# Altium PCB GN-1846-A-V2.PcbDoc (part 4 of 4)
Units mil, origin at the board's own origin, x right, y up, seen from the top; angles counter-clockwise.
Board outline 11624.17 x 2384.02 mil, 4 copper layers (Top, GND, VCC, Bottom), stack 40.7 mil thick; 450 components, 346 nets, 1652 pads, 832 vias.
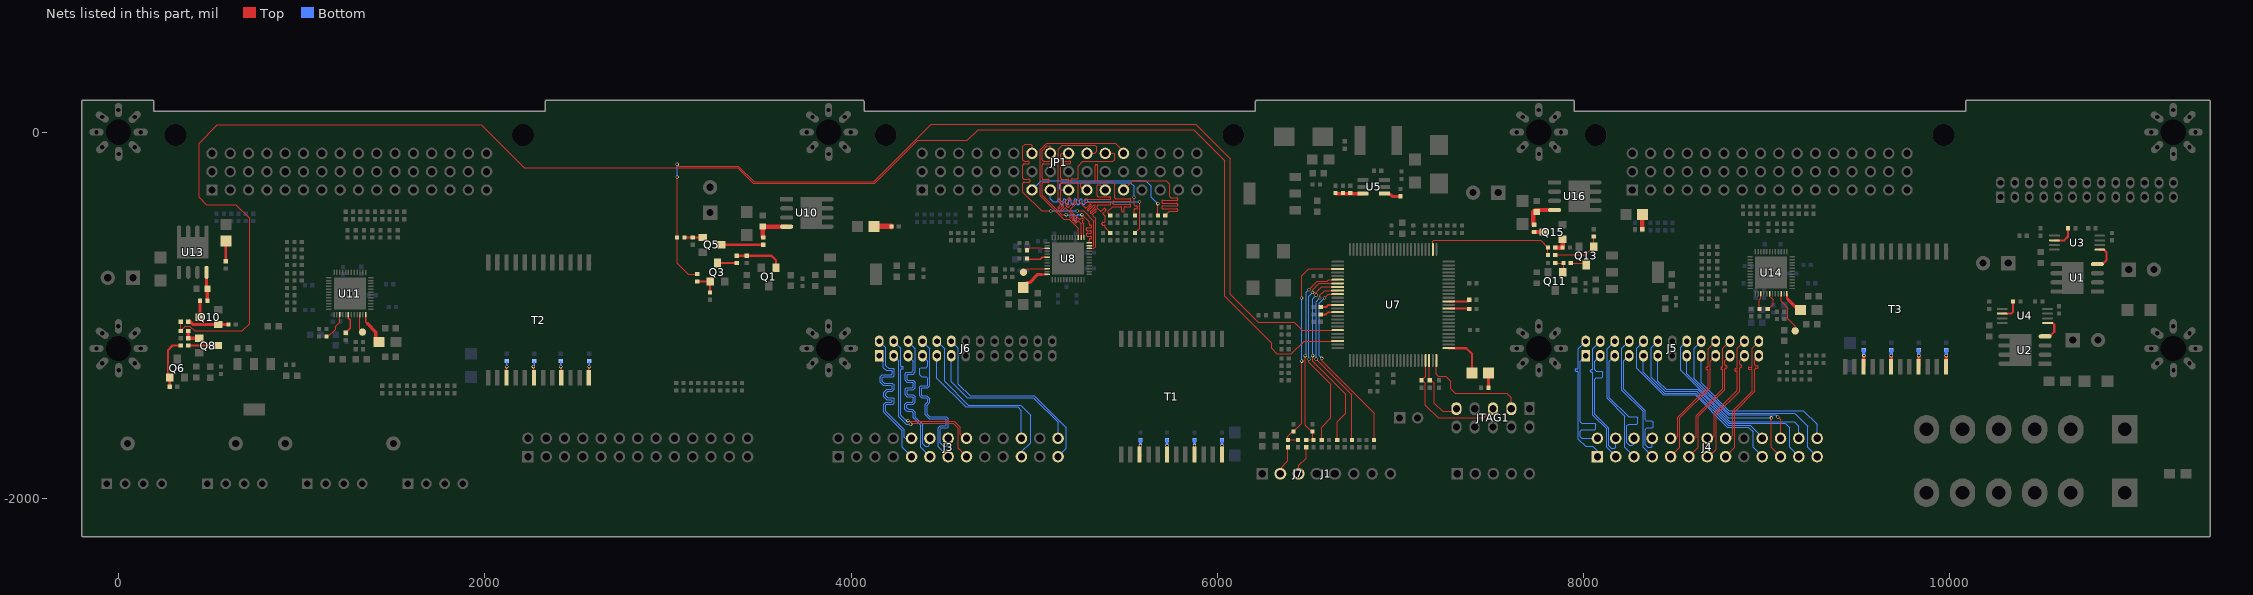
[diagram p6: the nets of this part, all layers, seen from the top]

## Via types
v1: diameter 18, hole 12, Top to Bottom, 768 vias
v2: diameter 24, hole 16, Top to Bottom, 34 vias
v3: diameter 30, hole 20, Top to Bottom, 27 vias
v4: diameter 40, hole 30, Top to Bottom, 2 vias
v5: diameter 24, hole 14, Top to Bottom, 1 vias

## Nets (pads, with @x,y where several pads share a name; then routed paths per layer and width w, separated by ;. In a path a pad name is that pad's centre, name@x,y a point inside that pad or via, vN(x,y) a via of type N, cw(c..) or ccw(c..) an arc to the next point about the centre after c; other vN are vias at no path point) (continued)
NetJTAG1_3: JTAG1.3 U7.25 | length 620.9
  Top w5: U7.25@7196.03,-1246.56 7196.03,-1321.03 7207,-1332 7247,-1332 7275,-1360 7275,-1401 7299,-1425 7580,-1425 7605,-1450 JTAG1.3@7605,-1510
NetJTAG1_5: JTAG1.5 R20.2 U7.22 | length 678.5
  Top w5: R20.2@7115,-1355 7136.97,-1333.03 U7.22@7136.97,-1246.56 ; R20.2@7120,-1355 7135,-1370 7135,-1490 7205,-1560 7455,-1560 JTAG1.5@7505,-1510
NetJTAG1_9: JTAG1.9 R21.1 U7.23 | length 378.8
  Top w5: U7.23@7156.66,-1246.56 7156.66,-1343.34 7185,-1371.68 7185,-1480 7230,-1525 JTAG1.9@7300,-1525
NetL3_2: L3.2 U8.48 | length 180.8
  Top w10: 5040,-776.61 U8.48@5070.04,-776.61
  Top w18: L3.2@4922.98,-858 4960,-820.98 4975.03,-820.98 5019.4,-776.61 5040,-776.61
NetL4_2: L4.2 U11.48 | length 179.5
  Top w10: U11.48@1349.76,-995.8 1349.76,-1036.53 1359.93,-1046.69
  Top w18: 1359.93,-1046.69 1405,-1091.77 1405,-1127 L4.2@1423,-1145
NetL5_2: L5.2 U14.48 | length 124
  Top w5: 9115,-911.85 9116.98,-913.83
  Top w10: U14.48@9110,-881.81 9110,-906.85 9115,-911.85
  Top w18: 9116.98,-913.83 L5.2@9180,-976.85
NetLED1_K: LED1.K R81.2 | length 94.8
  Top w30: LED1.K@4125.32,-514.61 4219.61,-514.61 R81.2@4220,-515
NetLED2_K: LED2.K R141.2 | length 109.8
  Top w15: R141.2@585,-705 585,-595.71 LED2.K@585.39,-595.32
NetLED3_A: LED3.A U7.26 | length 244.4
  Top w12: U7.26@7262.96,-1179.64 7359.64,-1179.64 7390.32,-1210.32 LED3.A@7390.32,-1314.61
NetLED3_K: LED3.K R7.2 | length 80.5
  Top w15: R7.2@7480,-1395 7480,-1314.94 LED3.K@7480.32,-1314.61
NetLED4_K: LED4.K R201.2 | length 80.5
  Top w24: R201.2@8320,-530 8320.32,-529.68 LED4.K@8320.32,-449.61
NetQ1_1: Q1.1 R58.2 R65.1 | length 265.4
  Top w12: R65.1@3375,-675 3565,-675 3590,-700 Q1.1@3590,-740
NetQ3_1: Q3.1 R73.1 R74.2 | length 130
  Top w12: R73.1@3160,-815 Q3.1@3230,-815 R74.2@3230,-875
NetQ3_3: Q3.3 R65.2 | length 105
  Top w12: Q3.3@3270,-715 R65.2@3375,-715
NetQ5_1: Q5.1 R82.1 R83.2 | length 100
  Top w12: R82.1@3090,-575 Q5.1@3190,-575
NetQ5_3: Q5.3 R80.1 | length 250
  Top w12: Q5.3@3270,-615 R80.1@3520,-615
NetQ6_1: Q6.1 R118.2 R127.1 | length 270.4
  Top w12: Q6.1@270,-1330 270,-1190 295,-1165 R127.1@340,-1165 ; R118.2@280,-1390 Q6.1@280,-1340
NetQ8_1: Q8.1 R133.1 R134.2 | length 100
  Top w18: R133.1@380,-1085 R134.2@380,-1125 Q8.1@440,-1125
NetQ8_3: Q8.3 R127.2 | length 160
  Top w12: R127.2@380,-1165 Q8.3@540,-1165
NetQ10_1: Q10.1 R142.1 R143.2 | length 219.7
  Top w18: R142.1@387.5,-1032.5 405,-1050 Q10.1@545,-1050 R143.2@600,-1050
NetQ10_3: Q10.3 R140.1 | length 90
  Top w18: Q10.3@445,-1010 R140.1@445,-920
NetQ11_1: Q11.1 R178.2 R186.1 | length 97.1
  Top w5: R178.2@7845,-715 R186.1@7890,-715 7890,-760 Q11.1@7885,-765
NetQ13_1: Q13.1 R193.1 R194.2 | length 283.6
  Top w5: R193.1@7845,-670 8010,-670 Q13.1@8055,-625 R194.2@8055,-570
NetQ13_3: Q13.3 R186.2 | length 89.1
  Top w5: R186.2@7930,-715 8005,-715 Q13.3@8015,-725
NetQ15_1: Q15.1 R202.1 R203.2 | length 85
  Top w24: R202.1@7845,-630 R203.2@7885,-630 Q15.1@7885,-585
NetQ15_3: Q15.3 R200.1 | length 60
  Top w24: R200.1@7725,-545 Q15.3@7785,-545
NetR5_1: R5.1 U3.2 | length 128.3
  Top w12: U3.2@10570.23,-590.64 10624.36,-590.64 10645,-570 R5.1@10645,-525
NetR6_1: R6.1 U4.2 | length 119.2
  Top w12: U4.2@10285.23,-990.64 10334.36,-990.64 10345,-980 R6.1@10345,-925
NetR8_2: R8.2 U5.4 | length 93.3
  Top w16: U5.4@6912.72,-335.58 6940.58,-335.58 6955,-350 R8.2@7000,-350
NetR9_2: R9.2 R10.2 R11.1 U5.3 | length 150.4
  Top w18: R10.2@6645.51,-332.35 6648.75,-335.58 U5.3@6794.6,-335.58
NetR12_1: R12.1 R425.2 R432.2 U7.78 | length 1196.6
  Top w5: R425.2@6440,-1680 R12.1@6385,-1680 6385,-1660 6410,-1635 R432.2@6415,-1635 6460,-1590 v1(6460,-1250) ; v1(6460,-905) 6460,-785 6498.43,-746.57 U7.78@6656.66,-746.57
  Bottom w5: v1(6460,-1250) v1(6460,-905)
NetR13_1: R13.1 R424.2 R433.2 U7.81 | length 1069
  Top w5: v1(6480,-1220) 6480,-1600 6515,-1635 R433.2@6520,-1635 6520,-1675 R424.2@6525,-1680 R13.1@6485,-1680 ; v1(6500,-860) 6545,-815 6600,-815 6609.38,-805.62 U7.81@6656.66,-805.62
  Bottom w5: v1(6480,-1220) 6485,-1215 6485,-875 v1(6500,-860)
NetR14_1: R14.1 U7.82 | length 1049.6
  Top w5: v1(6500,-1240) 6500,-1255 6620,-1375 6620,-1560 6570,-1610 R14.1@6570,-1680 ; v1(6520,-875) 6520,-860.31 6555,-825.31 U7.82@6656.66,-825.31
  Bottom w5: v1(6500,-1240) 6500,-895 v1(6520,-875)
NetR15_1: R15.1 U7.83 | length 1035.6
  Top w5: v1(6520,-1220) 6520,-1250 6700,-1430 6700,-1535 6655,-1580 R15.1@6655,-1680 ; v1(6540,-890) 6540,-874.99 6570,-844.99 U7.83@6656.66,-844.99
  Bottom w5: v1(6520,-1220) 6520,-910 v1(6540,-890)
NetR16_1: R16.1 U7.84 | length 986.2
  Top w5: v1(6540,-1240) 6735,-1435 R16.1@6735,-1680 ; v1(6560,-905) 6560,-890 6585.32,-864.68 U7.84@6656.66,-864.68
  Bottom w5: v1(6540,-1240) 6540,-925 v1(6560,-905)
NetR17_2: R17.2 U7.88 | length 96.5
  Top w10: R17.2@6565,-955 6593.42,-955 6605,-943.42 U7.88@6656.66,-943.42
NetR18_2: R18.2 U7.90 | length 96.7
  Top w10: R18.2@6565,-995 6592.79,-995 6605,-982.79 U7.90@6656.66,-982.79
NetR22_1: R22.1 U7.37 | length 117.5
  Top w10: U7.37@7262.96,-963.1 R22.1@7380.41,-963.1
NetR23_1: R23.1 U7.39 | length 112.3
  Top w10: U7.39@7262.96,-923.73 R23.1@7375.26,-923.73
NetR24_1: R24.1 T1.15 | length 89.8
  Top w15: v1@5576.14,-1713.86 5576.14,-1770.8 T1.15@5578.15,-1768.79
  Bottom w15: v1(5580,-1710) R24.1@5580,-1680
NetR25_1: R25.1 T1.18 | length 93.9
  Top w15: T1.18@5723.15,-1767.81 5726.14,-1770.8 v1@5726.14,-1711.14
  Bottom w15: v1(5725,-1710) R25.1@5725,-1680
NetR26_1: R26.1 T1.21 | length 92.5
  Top w15: v1@5876.14,-1711.14 5876.14,-1770.8 T1.21@5878.15,-1768.79
  Bottom w15: v1(5875,-1710) R26.1@5875,-1680
NetR32_1: R32.1 T1.24 | length 92.5
  Top w15: v1@6026.14,-1711.14 6026.14,-1770.8 T1.24@6028.15,-1768.79
  Bottom w15: v1(6025,-1710) R32.1@6025,-1680
NetR39_2: R39.2 U8.42 | length 147.6
  Top w8: R39.2@4960,-690 4964.16,-694.16 5005,-694.16 ; 4974.16,-694.16 5005,-694.16 ; U8.42@5070.04,-682.13 5043.88,-682.13 5031.85,-694.16 5005,-694.16
NetR43_2: R43.2 U8.39 | length 117.9
  Top w5: R43.2@4960,-645 4974.5,-630.5 5038.19,-630.5 5042.57,-634.88 U8.39@5070.04,-634.88
NetR73_2: R73.2 R82.2 U7.95 | length 5349.8
  Top w5: v1(3050,-245) R82.2@3050,-575 3050,-715 3110,-775 R73.2@3160,-775 ; v1(3050,-175) 3060,-185 3385,-185 3470,-270 4125,-270 4438.16,43.16 5882.55,43.16 6070,-144.29 6070,-884.29 6223.71,-1038 6420,-1038 6463.21,-1081.21 U7.95@6656.66,-1081.21
  Bottom w5: v1(3050,-245) v1(3050,-175)
NetR77_1: R77.1 R80.2 U10.4 | length 189.9
  Top w24: R80.2@3520,-575 3518.15,-573.15 R77.1@3518.15,-515.84 U10.4@3648.15,-515.84
NetR84_1: R84.1 T2.15 | length 91.6
  Top w8: T2.15@2118.15,-1340.8 2118.15,-1281.85 v1(2120,-1280)
  Bottom w8: v1(2120,-1280) R84.1@2120,-1250
NetR85_1: R85.1 T2.18 | length 89.7
  Top w8: T2.18@2268.15,-1340.8 v1@2268.15,-1283.15
  Bottom w8: v1(2265,-1280) 2270,-1275 R85.1@2270,-1250
NetR86_1: R86.1 T2.21 | length 92.1
  Top w8: v1(2415,-1280) 2418.15,-1283.15 T2.21@2418.15,-1340.8
  Bottom w8: v1(2415,-1280) R86.1@2415,-1250
NetR92_1: R92.1 T2.24 | length 91.6
  Top w8: T2.24@2568.15,-1340.8 2568.15,-1281.85 v1(2570,-1280)
  Bottom w8: v1(2570,-1280) R92.1@2570,-1250
NetR96_2: R96.2 U11.42 | length 113.6
  Top w8: R96.2@1240,-1095 1265,-1070 1265,-1024.72 1255.28,-1015 U11.42@1255.28,-995.8
NetR100_2: R100.2 U11.39 | length 155.3
  Top w5: R100.2@1135,-1115 1145,-1115 1185,-1075 1185,-1060 1208.03,-1036.97 U11.39@1208.03,-995.8
NetR133_2: R133.2 R142.2 U7.98 | length 9147.6
  Top w5: R142.2@340,-1040 R133.2@340,-1085 365,-1060 390,-1060 415,-1085 675,-1085 715,-1045 715,-470 640,-395 480,-395 440,-355 440,-60 540,40 1980,40 2215,-195 3380.86,-195 3465.86,-280 4129.14,-280 4364.14,-45 4635,-45 4693.16,13.16 5870.13,13.16 6040,-156.72 6040,-896.72 6296,-1152.72 6296,-1181 6325,-1210 6404,-1210 6473.73,-1140.27 U7.98@6656.66,-1140.27
NetR136_1: R136.1 R140.2 U13.4 | length 159.6
  Top w18: U13.4@480.24,-765.21 480.24,-855 R136.1@485,-855 R140.2@485,-920
NetR144_1: R144.1 T3.15 | length 91.6
  Top w18: T3.15@9528.15,-1280.8 9530,-1278.95 v1(9530,-1220)
  Bottom w18: v1(9530,-1220) R144.1@9530,-1190
NetR145_1: R145.1 T3.18 | length 91.6
  Top w18: T3.18@9678.15,-1280.8 9680,-1278.95 v1(9680,-1220)
  Bottom w18: v1(9680,-1220) R145.1@9680,-1190
NetR146_1: R146.1 T3.21 | length 91.6
  Top w18: T3.21@9828.15,-1280.8 9830,-1278.95 v1(9830,-1220)
  Bottom w18: v1(9830,-1220) R146.1@9830,-1190
NetR152_1: R152.1 T3.24 | length 91.6
  Top w18: T3.24@9978.15,-1280.8 9980,-1278.95 v1(9980,-1220)
  Bottom w18: v1(9980,-1220) R152.1@9980,-1190
NetR156_2: R156.2 U14.42 | length 106.6
  Top w5: R156.2@9005,-965 9010,-965 9035,-940 9035,-915 9015.52,-895.52 U14.42@9015.52,-881.81
NetR160_2: R160.2 U14.39 | length 86.8
  Top w5: R160.2@8960,-965 8960,-915 8968.27,-906.73 U14.39@8968.27,-881.81 U14.39@8968.39,-881.93
NetR193_2: R193.2 R202.2 U7.52 | length 731.3
  Top w5: U7.52@7176.34,-640.27 7176.34,-595.66 7181,-591 7766,-591 R202.2@7805,-630 R193.2@7805,-670
NetR197_1: R197.1 R200.2 U16.4 | length 190.4
  Top w24: R200.2@7725,-505 7725,-435 7735.16,-424.84 U16.4@7841.15,-424.84
NetR303_1: R303.1 U7.85 | length 993.1
  Top w5: v1(6570,-1235) 6570,-1249.14 6856.5,-1535.64 6856.5,-1678.5 R303.1@6855,-1680 ; v1(6585,-905) 6605.64,-884.36 U7.85@6656.66,-884.36
  Bottom w5: v1(6570,-1235) 6555,-1220 6555,-935 v1(6585,-905)
NetTP1_1: TP1.1 U8.46 | length 136.6
  Top w5: TP1.1@4941.59,-764.87 4961.34,-745.12 U8.46@5070.04,-745.12
NetTP2_1: TP2.1 U11.46 | length 101.4
  Top w5: U11.46@1318.27,-995.8 1318.27,-1077.89 TP2.1@1331.95,-1091.57
NetTP3_1: TP3.1 U14.46 | length 234.9
  Top w5: U14.46@9078.51,-881.81 9078.51,-923.51 9115,-960 9115,-1020 9155,-1060 TP3.1@9155,-1085
NetU1_4: U1.4 U3.5 | length 145.5
  Top w12: U1.4@10805,-720 10835,-720 10855,-700 10855,-655 10841.82,-641.82 U3.5@10818.26,-641.82
NetU2_4: U2.4 U4.5 | length 194
  Top w10: U2.4@10500,-1115 U2.4@10520,-1115 U2.4@10545,-1115 ; U4.5@10523.26,-1041.82 U4.5@10533.26,-1041.82 U4.5@10556.82,-1041.82
  Top w12: U4.5@10533.26,-1041.82 10561.82,-1041.82 10570,-1050 10570,-1090 U2.4@10545,-1115
RGMII_RXCK: JP1.C11 R27.1 | length 840.3
  Top w5: 5367.57,-430.16 cw(c5363.86,-426.44) 5360.16,-430.16 5345,-415 5345,-402.75 cw(c5350.25,-402.75) 5350.25,-397.5 5412.75,-397.5 ccw(c5412.75,-392.25) 5418,-392.25 5418,-387.75 ccw(c5412.75,-387.75) 5412.75,-382.5 5277.25,-382.5 cw(c5277.25,-377.25) 5272,-377.25 5272,-372.75 cw(c5277.25,-372.75) 5277.25,-367.5 5412.75,-367.5 ccw(c5412.75,-362.25) 5418,-362.25 5418,-357.75 ccw(c5412.75,-357.75) 5412.75,-352.5 5350.25,-352.5 cw(c5350.25,-347.25) 5345,-347.25 5345,-290 5347.39,-287.61 5360,-287.61 JP1.C11@5387.8,-315.41 ; 5367.57,-430.15 5379.95,-417.78 ; 5379.96,-417.77 cw(c5383.66,-421.49) 5387.36,-417.77 ; 5387.37,-417.78 5390.56,-420.96 cw(c5386.84,-424.67) 5390.56,-428.37 5375,-443.94 ccw(c5375.53,-444.47) 5375,-445 5387.8,-457.8 5387.8,-487.25 cw(c5382.55,-487.25) 5382.55,-492.5 5375.05,-492.5 ccw(c5375.05,-497.75) 5369.8,-497.75 5369.8,-502.25 ccw(c5375.05,-502.25) 5375.05,-507.5 5382.55,-507.5 cw(c5382.55,-512.75) 5387.8,-512.75 5387.8,-522.8 R27.1@5415,-550
RGMII_RXD0: JP1.C7 R29.1 | length 860
  Top w5: R29.1@5675,-455 v1(5675,-390)
  Bottom w5: JP1.C7@4987.8,-315.41 5038.2,-265 5610,-265 5640,-295 5640,-355 v1(5675,-390)
RGMII_RXD1: JP1.C8 R30.1 | length 977
  Top w5: R30.1@5550,-550 5575,-525 v1(5575,-380)
  Bottom w5: JP1.C8@5087.8,-315.41 5087.8,-362.8 5105,-380 5120,-380 ccw(c5120,-372.5) 5127.5,-372.5 cw(c5135,-372.5) 5135,-365 cw(c5135,-372.5) 5142.5,-372.5 5142.5,-387.5 ccw(c5150,-387.5) 5150,-395 ccw(c5150,-387.5) 5157.5,-387.5 5157.5,-372.5 cw(c5165,-372.5) 5165,-365 cw(c5165,-372.5) 5172.5,-372.5 5172.5,-387.5 ccw(c5180,-387.5) 5180,-395 ccw(c5180,-387.5) 5187.5,-387.5 5187.5,-372.5 cw(c5195,-372.5) 5195,-365 cw(c5195,-372.5) 5202.5,-372.5 5202.5,-387.5 ccw(c5210,-387.5) 5210,-395 ccw(c5210,-387.5) 5217.5,-387.5 5217.5,-372.5 cw(c5225,-372.5) 5225,-365 cw(c5225,-372.5) 5232.5,-372.5 5232.5,-387.5 ccw(c5240,-387.5) 5240,-395 ccw(c5240,-387.5) 5247.5,-387.5 5247.5,-372.5 cw(c5255,-372.5) 5255,-365 cw(c5255,-372.5) 5262.5,-372.5 5262.5,-387.5 ccw(c5270,-387.5) 5270,-395 ccw(c5270,-387.5) 5277.5,-387.5 5277.5,-372.5 cw(c5285,-372.5) 5285,-365 cw(c5285,-372.5) 5292.5,-372.5 5292.5,-377.5 ccw(c5295,-377.5) 5295,-380 v1(5575,-380)
RGMII_RXD2: JP1.C9 R31.1 | length 678.2
  Top w5: R31.1@5545,-450 5545,-422.75 cw(c5550.25,-422.75) 5550.25,-417.5 5558.75,-417.5 ccw(c5558.75,-412.25) 5564,-412.25 5564,-407.75 ccw(c5558.75,-407.75) 5558.75,-402.5 5550.25,-402.5 cw(c5550.25,-397.25) 5545,-397.25 v1(5545,-355)
  Bottom w5: JP1.C9@5189.59,-315.41 JP1.C9@5187.8,-315.41 5145.41,-315.41 5140,-310 5140,-285 5150,-275 5525,-275 5545,-295 v1(5545,-355)
RGMII_RXD3: JP1.C10 R33.1 | length 1031.8
  Top w5: JP1.C10@5287.8,-315.41 5270.41,-315.41 5255,-300 5255,-280 5265,-270 5327.25,-270 ccw(c5327.25,-264.75) 5332.5,-264.75 5332.5,-182.25 cw(c5337.75,-182.25) 5337.75,-177 5342.25,-177 cw(c5342.25,-182.25) 5347.5,-182.25 5347.5,-264.75 ccw(c5352.75,-264.75) 5352.75,-270 5425,-270 5440,-285 5440,-357.25 ccw(c5445.25,-357.25) 5445.25,-362.5 5522.75,-362.5 cw(c5522.75,-367.75) 5528,-367.75 5528,-372.25 cw(c5522.75,-372.25) 5522.75,-377.5 5434.24,-377.5 ccw(c5434.24,-382.75) 5428.99,-382.75 5428.99,-387.25 ccw(c5434.24,-387.25) 5434.24,-392.5 5522.75,-392.5 cw(c5522.75,-397.75) 5528,-397.75 5528,-402.25 cw(c5522.75,-402.25) 5522.75,-407.5 5497.75,-407.5 ccw(c5497.75,-412.75) 5492.5,-412.75 5492.5,-429.81 cw(c5487.25,-429.81) 5487.25,-435.06 5482.75,-435.06 cw(c5482.75,-429.81) 5477.5,-429.81 5477.5,-412.75 ccw(c5472.25,-412.75) 5472.25,-407.5 5427.5,-407.5 5405,-430 5405,-445 R33.1@5415,-455
RGMII_RXDV: JP1.C12 R28.1 | length 877.8
  Top w5: JP1.C12@5487.8,-315.41 5538.2,-265 5720,-265 5740,-285 5740,-350 ccw(c5747.5,-350) 5747.5,-357.5 5777.5,-357.5 cw(c5777.5,-365) 5785,-365 cw(c5777.5,-365) 5777.5,-372.5 5702.5,-372.5 ccw(c5702.5,-380) 5695,-380 ccw(c5702.5,-380) 5702.5,-387.5 5777.5,-387.5 cw(c5777.5,-395) 5785,-395 cw(c5777.5,-395) 5777.5,-402.5 5702.5,-402.5 ccw(c5702.5,-410) 5695,-410 ccw(c5702.5,-410) 5702.5,-417.5 5777.5,-417.5 cw(c5777.5,-425) 5785,-425 cw(c5777.5,-425) 5777.5,-432.5 5737.5,-432.5 R28.1@5715,-455
RGMII_TXCKOUT: JP1.A11 U8.22 | length 1092.3
  Top w5: U8.22@5299.96,-634.88 5326.13,-634.88 5335,-626.01 5335,-470 5320.05,-455.05 cw(c5323.59,-451.52) 5320.05,-447.98 5337.71,-430.33 ccw(c5334.17,-426.8) 5337.71,-423.26 ccw(c5334.17,-426.8) 5330.63,-423.26 5312.98,-440.91 cw(c5309.45,-437.38) 5305.91,-440.91 cw(c5309.45,-437.38) 5305.91,-433.84 5332.54,-407.21 ccw(c5329,-403.68) 5332.54,-400.14 ccw(c5329,-403.68) 5325.47,-400.14 5298.84,-426.77 cw(c5295.3,-423.23) 5291.77,-426.77 cw(c5295.3,-423.23) 5291.77,-419.7 5309.43,-402.03 ccw(c5305.9,-398.5) 5309.43,-394.96 ccw(c5305.9,-398.5) 5302.36,-394.96 5284.7,-412.63 cw(c5281.16,-409.09) 5277.63,-412.63 5240,-375 5240,-283 ccw(c5232,-283) 5232,-275 5208.56,-275 cw(c5208.56,-267) 5200.56,-267 5200.56,-263 cw(c5208.56,-263) 5208.56,-255 5232,-255 ccw(c5232,-247) 5240,-247 5240,-185 5265,-160 5430,-160 5440,-150 5440,-120 5435.41,-115.41 JP1.A11@5387.8,-115.41
RGMII_TXD0: JP1.A7 U8.23 | length 1085.1
  Top w5: JP1.A7@4987.8,-115.41 4987.8,-72.8 4980,-65 4950,-65 4938.15,-76.85 4938.15,-150 ccw(c4945.65,-150) 4945.65,-157.5 4965.65,-157.5 cw(c4965.65,-165) 4973.15,-165 cw(c4965.65,-165) 4965.65,-172.5 4945.65,-172.5 ccw(c4945.65,-180) 4938.15,-180 4938.15,-250 ccw(c4945.65,-250) 4945.65,-257.5 4970.65,-257.5 cw(c4970.65,-265) 4978.15,-265 cw(c4970.65,-265) 4970.65,-272.5 4945.65,-272.5 ccw(c4945.65,-280) 4938.15,-280 4938.15,-328.15 5040,-430 v1(5090,-430) ; v1(5235,-430) 5270,-430 5325,-485 5325,-616.01 5321.88,-619.13 U8.23@5299.96,-619.13
  Bottom w5: v1(5090,-430) v1(5235,-430)
RGMII_TXD1: JP1.A8 U8.24 | length 1087.2
  Top w5: JP1.A8@5087.8,-115.41 5087.8,-77.8 5085,-75 5069.55,-75 5043.15,-101.4 5043.15,-150 ccw(c5050.65,-150) 5050.65,-157.5 5085.65,-157.5 cw(c5085.65,-165) 5093.15,-165 cw(c5085.65,-165) 5085.65,-172.5 5050.65,-172.5 ccw(c5050.65,-180) 5043.15,-180 5043.15,-250 ccw(c5050.65,-250) 5050.65,-257.5 5075.65,-257.5 cw(c5075.65,-265) 5083.15,-265 cw(c5075.65,-265) 5075.65,-272.5 5050.65,-272.5 ccw(c5050.65,-280) 5043.15,-280 5043.15,-343.15 5150,-450 v1(5175,-450) ; v1(5260,-450) 5299.96,-489.96 5299.96,-500.96 ccw(c5306.5,-500.96) 5306.5,-507.5 cw(c5306.5,-515) 5314,-515 cw(c5306.5,-515) 5306.5,-522.5 5290.11,-522.5 ccw(c5290.11,-530) 5282.61,-530 ccw(c5290.11,-530) 5290.11,-537.5 5306.5,-537.5 cw(c5306.5,-545) 5314,-545 cw(c5306.5,-545) 5306.5,-552.5 5291.2,-552.5 ccw(c5291.2,-560) 5283.7,-560 ccw(c5291.2,-560) 5291.2,-567.5 5306.5,-567.5 cw(c5306.5,-575) 5314,-575 cw(c5306.5,-575) 5306.5,-582.5 ccw(c5306.5,-589.04) 5299.96,-589.04 U8.24@5299.96,-603.39
  Bottom w5: v1@5180,-450 5210,-450 cw(c5210,-457.5) 5217.5,-457.5 5217.5,-477.5 ccw(c5225,-477.5) 5225,-485 ccw(c5225,-477.5) 5232.5,-477.5 5232.5,-457.5 cw(c5240,-457.5) 5240,-450 v1(5260,-450)
RGMII_TXD2: JP1.A9 U8.25 | length 921.2
  Top w5: 5185.62,-361.18 5164.41,-382.39 cw(c5159.11,-377.09) 5153.81,-382.39 5144.56,-373.15 5144.56,-280 cw(c5152.06,-280) 5152.06,-272.5 5182.06,-272.5 ccw(c5182.06,-265) 5189.56,-265 ccw(c5182.06,-265) 5182.06,-257.5 5152.06,-257.5 cw(c5152.06,-250) 5144.56,-250 5144.56,-180 cw(c5152.06,-180) 5152.06,-172.5 5192.06,-172.5 ccw(c5192.06,-165) 5199.56,-165 ccw(c5192.06,-165) 5192.06,-157.5 5152.06,-157.5 cw(c5152.06,-150) 5144.56,-150 5144.56,-120 5149.16,-115.41 JP1.A9@5187.8,-115.41 ; 5185.63,-361.17 cw(c5190.93,-366.48) 5196.23,-361.18 cw(c5190.93,-366.48) 5196.23,-371.78 5175.02,-393 ccw(c5180.32,-398.3) 5175.01,-403.6 5178.89,-407.47 ccw(c5184.19,-402.17) 5189.49,-407.48 5217.78,-379.19 cw(c5223.08,-384.49) 5228.38,-379.19 cw(c5223.08,-384.49) 5228.39,-389.79 5200.1,-418.08 ccw(c5205.4,-423.38) 5200.1,-428.68 5243.78,-472.36 ccw(c5249.08,-467.06) 5254.38,-472.36 5255.29,-471.45 cw(c5260.59,-476.75) 5265.9,-471.45 cw(c5260.59,-476.75) 5265.9,-482.06 5264.99,-482.97 ccw(c5270.29,-488.27) 5264.99,-493.57 ; 5264.99,-493.57 5271.61,-500.2 U8.25@5271.61,-575.04
RGMII_TXD3: JP1.A10 U8.26 | length 1023.5
  Top w5: 5144.63,-423.42 5159.13,-408.93 ccw(c5156.3,-406.1) 5159.13,-403.27 5157.71,-401.86 ccw(c5154.89,-404.68) 5152.06,-401.86 5137.56,-416.35 cw(c5134.73,-413.52) 5131.91,-416.35 5130.49,-414.94 cw(c5133.32,-412.11) 5130.49,-409.28 5144.99,-394.79 ccw(c5142.16,-391.96) 5144.99,-389.13 5132.15,-376.29 5132.15,-91.84 5153.15,-70.84 5330.84,-70.84 5340,-80 5340,-105 5329.59,-115.41 JP1.A10@5287.8,-115.41 ; 5144.63,-423.42 ccw(c5147.46,-426.25) 5144.63,-429.08 5146.05,-430.49 ccw(c5148.88,-427.66) 5151.7,-430.49 5166.2,-416 cw(c5169.03,-418.83) 5171.86,-416 5202.22,-446.36 cw(c5199.39,-449.19) 5202.22,-452.02 5195.16,-459.08 ccw(c5197.99,-461.9) 5195.16,-464.73 5196.58,-466.15 ccw(c5199.41,-463.32) 5202.24,-466.15 5209.29,-459.09 cw(c5212.12,-461.92) 5214.95,-459.09 5216.36,-460.51 cw(c5213.53,-463.33) 5216.36,-466.16 5209.37,-473.16 ccw(c5212.2,-475.99) 5209.37,-478.81 5210.78,-480.23 ccw(c5213.61,-477.4) 5216.44,-480.23 5223.43,-473.23 cw(c5226.26,-476.06) 5229.09,-473.23 5230.51,-474.65 cw(c5227.68,-477.48) 5230.51,-480.3 5223.51,-487.3 ccw(c5226.34,-490.13) 5223.51,-492.96 5224.92,-494.37 ccw(c5227.75,-491.54) 5230.58,-494.37 5237.58,-487.38 cw(c5240.4,-490.2) 5243.23,-487.38 5255.87,-500.01 5255.87,-555 U8.26@5255.87,-575.04
RGMII_TXEN: JP1.A12 U8.27 | length 1081.7
  Top w5: U8.27@5240.12,-575.04 5240.12,-555 5240.12,-525.12 5190,-475 5160,-475 5032.11,-347.11 5032.11,-96.87 5069.15,-59.84 5442.15,-59.84 5442.31,-60 5487.8,-105.48 JP1.A12@5487.8,-115.41
RXD: J1.2 J7.2 R12.2 | length 161.6
  Top w6: J1.2@6345,-1865 6345,-1835 6385,-1795 R12.2@6385,-1720
TXD: J1.3 J7.3 R13.2 | length 161.6
  Top w6: J1.3@6445,-1865 6445,-1820 6485,-1780 R13.2@6485,-1720
UPA-BG+: J4.24 J5.11 | length 1077.5
  Bottom w5: J5.11@8405.51,-1220.47 8405.51,-1360.51 8450,-1405 8621.72,-1405 8796.72,-1580 9150,-1580 9175,-1605 J4.24@9175,-1671.65
UPA-BG-: J4.23 J5.12 | length 1258.7
  Bottom w5: J5.12@8405.51,-1141.73 8370,-1177.24 8370,-1339.14 8445.86,-1415 8617.57,-1415 8792.57,-1590 9100,-1590 9125,-1615 9125,-1721.65 J4.23@9175,-1771.65
UPA-BY+: J4.20 J5.9 | length 892.5
  Bottom w5: J5.9@8326.77,-1220.47 8326.77,-1311.77 8440,-1425 8613.43,-1425 8788.43,-1600 8910,-1600 8975,-1665 J4.20@8975,-1671.65
UPA-BY-: J4.19 J5.10 | length 1098.8
  Bottom w5: J5.10@8326.77,-1141.73 8290,-1178.5 8290,-1290 8435,-1435 8609.29,-1435 8784.29,-1610 8900,-1610 8925,-1635 8925,-1721.65 J4.19@8975,-1771.65
UPA_MX1_N: J4.8 J5.7 | length 707
  Bottom w6: J5.7@8248.03,-1220.47 8220,-1248.5 8220,-1404.44 8336,-1520.44 8336,-1571 8340,-1575 8370,-1575 8380,-1585 8380,-1610 8375,-1615 8345,-1615 8336,-1624 8336,-1706 8350,-1720 8370,-1720 8375,-1715 J4.8@8375,-1671.65
UPA_MX1_P: J4.7 J5.8 | length 714.8
  Bottom w6: J5.8@8248.03,-1141.73 8209,-1180.76 8209,-1409 8325,-1525 8325,-1721.65 J4.7@8375,-1771.65
UPA_MX2_N: J4.6 J5.5 | length 706
  Bottom w6: J5.5@8169.29,-1220.47 8140,-1249.76 8140,-1449.44 8245.56,-1555 8290,-1555 8295,-1560 8295,-1590 8290,-1595 8245,-1595 8236,-1604 8236,-1696 8250,-1710 8265,-1710 8275,-1700 J4.6@8275,-1671.65
UPA_MX2_P: J4.5 J5.6 | length 707.1
  Bottom w6: J5.6@8169.29,-1141.73 8129,-1182.02 8129,-1454 8225,-1550 8225,-1721.65 J4.5@8275,-1771.65
UPA_MX3_N: J4.2 J5.1 | length 702.8
  Bottom w6: J5.1@8011.81,-1220.47 7981.91,-1250.38 7981.91,-1581.91 7990,-1590 8060,-1590 8065,-1595 8065,-1620 8060,-1625 7990,-1625 7981.91,-1633.09 7981.91,-1663.56 7990,-1671.65 J4.2@8075,-1671.65
UPA_MX3_P: J4.1 J5.2 | length 707.1
  Bottom w6: J5.2@8011.81,-1141.73 7970,-1183.54 7970,-1287.6 cw(c7964.6,-1287.6) 7964.6,-1293 7958.64,-1293 ccw(c7958.64,-1298.4) 7953.24,-1298.4 7953.24,-1299.6 ccw(c7958.64,-1299.6) 7958.64,-1305 7964.6,-1305 cw(c7964.6,-1310.4) 7970,-1310.4 7970,-1675.56 8010.44,-1716 8051,-1716 8075,-1740
UPA_MX4_N: J4.4 J5.3 | length 700.8
  Bottom w6: J5.3@8090.55,-1220.47 8060.91,-1250.12 8060.91,-1295.91 8070,-1305 8100,-1305 8105,-1310 8105,-1335 8100,-1340 8070,-1340 8060.91,-1349.09 8060.91,-1540.91 8136,-1616 8136,-1711 8150,-1725 8170,-1725 8175,-1720 J4.4@8175,-1671.65
UPA_MX4_P: J4.3 J5.4 | length 714.1
  Bottom w6: J5.4@8090.55,-1141.73 8049,-1183.28 8049,-1292.6 cw(c8043.6,-1292.6) 8043.6,-1298 8042.4,-1298 ccw(c8042.4,-1303.4) 8037,-1303.4 8037,-1304.6 ccw(c8042.4,-1304.6) 8042.4,-1310 8043.6,-1310 cw(c8043.6,-1315.4) 8049,-1315.4 8049,-1544.56 8125,-1620.56 8125,-1721.65 J4.3@8175,-1771.65
UPBMX1_N: J3.14 J6.8 | length 874
  Bottom w6: J6.8@4389.76,-1141.73 4430,-1181.97 4430,-1385.56 4419.56,-1396 4389,-1396 4386,-1399 4386,-1435.44 4389.56,-1439 4413.56,-1439 4430,-1455.44 4430,-1475.56 4414.56,-1491 4414.56,-1539 4430.56,-1555 4520,-1555 4530,-1565 4530,-1610 4525,-1615 4490,-1615 4486,-1619 4486,-1696 4505,-1715 4520,-1715 4530,-1705 J3.14@4530,-1671.65
UPBMX1_P: J3.13 J6.7 | length 866.5
  Bottom w6: J6.7@4389.76,-1220.47 4389.76,-1220.76 4419,-1250 4419,-1275 4409,-1285 4380,-1285 4375,-1290 4375,-1325 4385,-1335 4409,-1335 4419,-1345 4419,-1381 4415,-1385 4380,-1385 4375,-1390 4375,-1440 4385,-1450 4409,-1450 4419,-1460 4419,-1471 4403.56,-1486.44 4403.56,-1543.56 4426,-1566 4515,-1566 4519,-1570 4519,-1600 4515,-1604 4485.44,-1604 4475,-1614.44 4475,-1716.65 J3.13@4530,-1771.65
UPBMX2_N: J3.12 J6.6 | length 886.4
  Bottom w6: J6.6@4311.02,-1141.73 4351,-1181.71 4351,-1309 4339,-1321 4310,-1321 4306,-1325 4306,-1350.44 4309.56,-1354 4339.56,-1354 4351,-1365.44 4351,-1394.56 4339.56,-1406 4310,-1406 4306,-1410 4306,-1430.44 4309.56,-1434 4339.56,-1434 4351,-1445.44 4351,-1474.56 4339.56,-1486 4309,-1486 4305,-1490 4305,-1504.44 4314.56,-1514 4334.56,-1514 4351,-1530.44 4351,-1556 4390,-1595 4390,-1700 4405,-1715 4420,-1715 4430,-1705 J3.12@4430,-1671.65
UPBMX2_P: J3.11 J6.5 | length 839.4
  Bottom w6: J6.5@4290.53,-1220.47 J6.5@4311.02,-1220.47 4340,-1249.45 4340,-1300 4330,-1310 4300,-1310 4295,-1315 4295,-1355 4305,-1365 4335,-1365 4340,-1370 4340,-1390 4335,-1395 4300,-1395 4295,-1400 4295,-1435 4305,-1445 4335,-1445 4340,-1450 4340,-1470 4335,-1475 4304.44,-1475 4294,-1485.44 4294,-1514 4305,-1525 4330,-1525 4340,-1535 4340,-1560.56 4379,-1599.56 4379,-1720.65 J3.11@4430,-1771.65
UPBMX3_N: J3.10 J6.2 | length 876.1
  Bottom w6: J6.2@4153.54,-1141.73 4190,-1178.19 4190,-1275 4205,-1290 4230,-1290 4235,-1295 4235,-1330 4230,-1335 4175,-1335 4171,-1339 4171,-1361 4180,-1370 4225,-1370 4235,-1380 4235,-1405 4225,-1415 4200,-1415 4190,-1425 4190,-1440 4200,-1450 4230,-1450 4235,-1455 4235,-1480 4230,-1485 4195,-1485 4190,-1490 4190,-1524.44 4291,-1625.44 4291,-1666 4296.65,-1671.65 J3.10@4330,-1671.65
UPBMX3_P: J3.9 J6.1 | length 871.2
  Bottom w6: J6.1@4153.54,-1220.47 4153.54,-1228.54 4175,-1250 4175,-1285 4191,-1301 4221,-1301 4224,-1304 4224,-1320 4220,-1324 4170.44,-1324 4160,-1334.44 4160,-1365.56 4175.44,-1381 4220.44,-1381 4224,-1384.56 4224,-1400.44 4220.44,-1404 4195.44,-1404 4179,-1420.44 4179,-1444.56 4195.44,-1461 4220,-1461 4224,-1465 4224,-1470 4220,-1474 4190.44,-1474 4179,-1485.44 4179,-1529 4280,-1630 4280,-1721.65 J3.9@4330,-1771.65
UPBMX4_N: J3.16 J6.4 | length 875.8
  Top w6: v1(4310,-1575) 4311,-1574 4315,-1578 4563,-1578 4596,-1611 4596,-1650 4617.65,-1671.65 J3.16@4630,-1671.65
  Bottom w6: J6.4@4232.28,-1141.73 4271,-1180.45 4271,-1275.6 ccw(c4276.4,-1275.6) 4276.4,-1281 4280.62,-1281 cw(c4280.62,-1286.4) 4286.02,-1286.4 4286.02,-1287.6 cw(c4280.62,-1287.6) 4280.62,-1293 4276.4,-1293 ccw(c4276.4,-1298.4) 4271,-1298.4 4271,-1546 4300,-1575 v1(4310,-1575)
UPBMX4_P: J3.15 J6.3 | length 875.8
  Top w6: v1@4330,-1595 4336,-1589 4558.44,-1589 4585,-1615.56 4585,-1726.65 J3.15@4630,-1771.65
  Bottom w6: J6.3@4232.28,-1220.47 4260,-1248.19 4260,-1555 4300,-1595 v1(4325,-1595) v1@4330,-1595
UPC-AG+: J4.26 J5.17 | length 951.7
  Bottom w5: J5.17@8641.73,-1220.47 8641.73,-1368.45 8793.28,-1520 9200,-1520 9275,-1595 J4.26@9275,-1671.65
UPC-AG-: J4.25 J5.18 | length 1134
  Bottom w5: J5.18@8641.73,-1141.73 8605,-1178.47 8605,-1345.86 8792.64,-1533.5 9153.5,-1533.5 9225,-1605 9225,-1721.65 J4.25@9275,-1771.65
UPC-AY+: J4.22 J5.15 | length 837.4
  Top w5: v1(9060,-1555) 9075,-1570 J4.22@9075,-1671.65
  Bottom w5: J5.15@8562.99,-1220.47 8562.99,-1317.99 8788.5,-1543.5 8915,-1543.5 ; 8936.83,-1543.5 8915,-1543.5 ; v1(9060,-1555) 9048.5,-1543.5 8915,-1543.5
UPC-AY-: J4.21 J5.16 | length 1006.5
  Top w5: v1(9025,-1560) 9025,-1721.65 J4.21@9075,-1771.65
  Bottom w5: J5.16@8562.99,-1141.73 8530,-1174.73 8530,-1299.14 8790.86,-1560 v1(9025,-1560)
UPC_MX1_N: J4.14 J5.24 | length 652.9
  Top w6: J4.14@8675,-1671.65 8703.35,-1671.65 8714,-1661 8714,-1536 8840,-1410 8840,-1310.4 ccw(c8834.6,-1310.4) 8834.6,-1305 8829.63,-1305 cw(c8829.63,-1299.6) 8824.23,-1299.6 8824.23,-1298.4 cw(c8829.63,-1298.4) 8829.63,-1293 8834.6,-1293 ccw(c8834.6,-1287.6) 8840,-1287.6 8840,-1179.69 J5.24@8877.95,-1141.73
UPC_MX1_P: J4.13 J5.23 | length 654.9
  Top w6: J4.13@8675,-1771.65 8683.35,-1771.65 8725,-1730 8725,-1540.56 8851,-1414.56 8851,-1288.4 cw(c8856.4,-1288.4) 8856.4,-1283 8857.6,-1283 ccw(c8857.6,-1277.6) 8863,-1277.6 8863,-1276.4 ccw(c8857.6,-1276.4) 8857.6,-1271 8856.4,-1271 cw(c8856.4,-1265.6) 8851,-1265.6 8851,-1247.43 J5.23@8877.95,-1220.47
UPC_MX2_N: J4.12 J5.22 | length 656.5
  Top w6: J4.12@8575,-1671.65 8607.35,-1671.65 8614,-1665 8614,-1547 8760,-1401 8760,-1300.4 ccw(c8754.6,-1300.4) 8754.6,-1295 8753.4,-1295 cw(c8753.4,-1289.6) 8748,-1289.6 8748,-1288.4 cw(c8753.4,-1288.4) 8753.4,-1283 8754.6,-1283 ccw(c8754.6,-1277.6) 8760,-1277.6 8760,-1180.95 J5.22@8799.21,-1141.73
UPC_MX2_P: J4.11 J5.21 | length 658.8
  Top w6: J4.11@8575,-1771.65 8625,-1721.65 8625,-1551.56 8771,-1405.56 8771,-1293.4 cw(c8776.4,-1293.4) 8776.4,-1288 8777.6,-1288 ccw(c8777.6,-1282.6) 8783,-1282.6 8783,-1281.4 ccw(c8777.6,-1281.4) 8777.6,-1276 8776.4,-1276 cw(c8776.4,-1270.6) 8771,-1270.6 8771,-1248.69 J5.21@8799.21,-1220.47
UPC_MX3_N: J4.10 J5.20 | length 662.9
  Top w6: J4.10@8475,-1671.65 8503.35,-1671.65 8514,-1661 8514,-1555.44 8679,-1390.44 8679,-1300.4 ccw(c8673.6,-1300.4) 8673.6,-1295 8672.4,-1295 cw(c8672.4,-1289.6) 8667,-1289.6 8667,-1288.4 cw(c8672.4,-1288.4) 8672.4,-1283 8673.6,-1283 ccw(c8673.6,-1277.6) 8679,-1277.6 8679,-1183.21 J5.20@8720.47,-1141.73
UPC_MX3_P: J4.9 J5.19 | length 654.4
  Top w6: J4.9@8475,-1771.65 8525,-1721.65 8525,-1560 8690.91,-1394.09 8690.91,-1295.86 8690,-1294.95 8690,-1283.05 8690.91,-1282.14 8690.91,-1272.67 8690,-1271.76 8690,-1250.95 J5.19@8720.47,-1220.47
UPC_MX4_N: J4.16 J5.26 | length 652.9
  Top w6: J4.16@8775,-1671.65 8798.35,-1671.65 8814,-1656 8814,-1521 8920,-1415 8920,-1300.4 ccw(c8914.6,-1300.4) 8914.6,-1295 8903.76,-1295 cw(c8903.76,-1289.6) 8898.36,-1289.6 8898.36,-1288.4 cw(c8903.76,-1288.4) 8903.76,-1283 8914.6,-1283 ccw(c8914.6,-1277.6) 8920,-1277.6 8920,-1178.43 J5.26@8956.69,-1141.73
UPC_MX4_P: J4.15 J5.25 | length 652.9
  Top w6: J4.15@8775,-1771.65 8825,-1721.65 8825,-1525.56 8935,-1415.56 8935,-1293.4 cw(c8940.4,-1293.4) 8940.4,-1288 8947.44,-1288 ccw(c8947.44,-1282.6) 8952.84,-1282.6 8952.84,-1281.4 ccw(c8947.44,-1281.4) 8947.44,-1276 8940.4,-1276 cw(c8940.4,-1270.6) 8935,-1270.6 8935,-1242.17 J5.25@8956.69,-1220.47
UPG+: J3.26 J6.11 | length 903.4
  Bottom w5: J6.11@4547.24,-1225 4547.24,-1362.24 4635,-1450 4995,-1450 5130,-1585 J3.26@5130,-1671.65
  Bottom w6: J6.11@4547.24,-1225 J6.11@4547.24,-1220.47
UPG-: J3.25 J6.12 | length 1113.6
  Bottom w5: J6.12@4547.24,-1141.73 4585,-1179.49 4585,-1375 4650,-1440 5000,-1440 5175,-1615 5175,-1726.65 J3.25@5130,-1771.65
UPY+: J3.22 J6.9 | length 808.7
  Bottom w5: J6.9@4468.5,-1230 4468.5,-1343.5 4625,-1500 4909,-1500 4930,-1521 J3.22@4930,-1671.65
  Bottom w6: J6.9@4468.5,-1230 J6.9@4468.5,-1220.47
UPY-: J3.21 J6.10 | length 1029.4
  Bottom w5: J6.10@4468.5,-1141.73 4510,-1183.23 4510,-1360 4640,-1490 4925,-1490 4980,-1545 4980,-1695 4930,-1745 J3.21@4930,-1771.65
pads on no net: C4.2 J8.15 J8.16 J8.17 J8.18 J8.23 J8.24 JP1.0 JP1.0/2 JP1.A14 JP1.A15 JP1.A16 JP1.B5 JP1.B6 JP1.C4 JP1.C5 JP1.C13 JP1.C14 JP1.C15 JP1.C16 JP2.0 JP2.0/2 JP2.A14 JP2.A15 JP2.A16 JP2.B5 JP2.B6 JP2.C4 JP2.C5 JP2.C13 JP2.C14 JP2.C15 JP2.C16 JP3.0 JP3.0/2 JP3.A14 JP3.A15 JP3.A16 JP3.B5 JP3.B6 JP3.C4 JP3.C5 JP3.C13 JP3.C14 JP3.C15 JP3.C16 JTAG1.6 JTAG1.7 JTAG1.8 M1.1 M2.1 M3.1 M4.1 M5.1 M6.1 M7.1 M8.1 U7.1 U7.7 U7.8 U7.12 U7.14 U7.15 U7.16 U7.17 U7.18 U7.19 U7.20 U7.21 U7.27 U7.28 U7.29 U7.30 U7.33 U7.34 U7.35 U7.36 U7.38 U7.40 U7.41 U7.42 U7.43 U7.44 U7.47 U7.48 U7.49 U7.50 U7.51 U7.58 U7.61 U7.62 U7.72 U7.73 U7.74 U7.75 U7.76 U7.77 U7.86 U7.87 U7.89 U7.91 U7.92 U8.12 U8.43 U11.12 U11.43 U14.12 U14.43 Y1.1

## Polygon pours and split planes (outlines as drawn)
GND on VCC "GND" (hatched 90Degree grid 5 track 5, remove dead copper, pour order 1000): -153.55,169.18 -180.82,169.18 -195,155 -196.85,153.15 -196.85,129 -196.85,-2073.15 -160,-2110 -156.3,-2106.3 -90,-2106.3 11388.7,-2106.3 11415,-2080 11417.32,-2077.68 11417.32,-2050 11417.32,147.68 11395,170 11394.29,169.29 11325,169.29 -153.44,169.29 -153.55,169.18
5V0 on VCC "5V0" (hatched 90Degree grid 5 track 5, remove dead copper, pour order 1002): 6705,-1345 6670,-1345 6670,-1330 6670,-1300 6670,-937.85 6672.15,-940 6698.15,-940 6702.15,-940 6705,-942.85 6705,-977.85 6705,-1345
12VIN on VCC "12VIN" (hatched 90Degree grid 5 track 5, remove dead copper, pour order 1000): 10426.27,-555 10238.52,-555 10238.52,-180 10238.52,-150 10091.37,-150 8259.53,-150 8259.53,-210 8259.53,-460 7884.03,-460 7163.47,-460 7163.47,-255 7163.47,-220 7163.47,-120 7163.47,-100 7148.25,-100 6361.73,-100 6361.73,-145 6361.73,-175 6260.24,-175 4342.14,-175 4342.14,-180 4342.14,-585 4189.91,-585 3068.48,-585 3068.48,-545 3068.48,-275 3043.11,-275 226.85,-275 226.85,-305 226.85,-940 -97.91,-940 -97.91,-895 -97.91,-670 -97.91,50 181.18,50 2368.22,50 2368.22,105 2388.52,105 2484.93,105 4017.38,105 4017.38,95 4088.42,95 4123.94,95 4890.17,95 6275.46,95 6275.46,135 6300.84,135 6356.65,135 7965.22,135 7965.22,95 7995.67,95 8071.78,95 10482.09,95 10482.09,10 10482.09,-550 10482.09,-555 10426.27,-555
12VIN on VCC "GND" (hatched 90Degree grid 5 track 5, remove dead copper, pour order 1000): 10478.15,95.69 10547.85,95.69 10550,97.85 10550,-542.15 10432.85,-542.15 10430,-545 10438.15,-536.85 10438.15,95.69 10477.87,95.69 10478.57,95
12VIN on VCC "GND" (hatched 90Degree grid 5 track 5, remove dead copper, pour order 1001): 965,-1610 965,-1695 965,-1795 860,-1795 125,-1795 120,-1790 120.59,-1789.41 120.59,-1180.83 120.59,-1025.59 55,-960 48.15,-953.15 48.15,-900 224.7,-900 226.85,-897.85 320,-991 320,-1360 320,-1570 350,-1600 360,-1610 965,-1610
5V0 on VCC "GND" (hatched 90Degree grid 5 track 5, remove dead copper, pour order 1002): 955,-1595 895,-1595 365,-1595 335,-1565 335,-1550 335,-985 240,-890 240,-880 240,-285 255,-285 3055,-285 3055,-305 3055,-600 3090,-600 4355,-600 4355,-580 4355,-190 4400,-190 6380,-190 6380,-160 6380,-115 6405,-115 7150,-115 7150,-120 7150,-470 7150,-475 7180,-475 8285,-475 8285,-170 8305,-170 10220,-170 10220,-175 10220,-575 10295,-575 10565,-575 10565,-500 10565,95 10580,95 10700,95 10700,80 10700,-675 10515,-860 10060,-860 10060,-600 9885,-425 9715,-425 8730,-425 8535,-620 8255,-900 7585,-900 6915,-900 6775,-1040 6770,-1045 6200,-1045 6025,-1045 5870,-890 5490,-510 5030,-510 4765,-510 4745,-530 4710,-565 4710,-815 4710,-885 4570,-1025 4310,-1025 2760,-1025 2650,-915 2650,-590 2650,-585 2550,-485 2540,-475 2335,-475 1770,-475 1575,-670 1545,-640 950,-640 950,-1590 955,-1595
GND on Bottom "GND" (hatched 90Degree grid 5 track 5, remove dead copper, pour order 1001): -140,169.18 -140.82,170 -175,170 -185,170 -195,160 -196.85,158.15 -196.85,120 -196.85,-2073.15 -165,-2105 -163.7,-2106.3 -80,-2106.3 11398.7,-2106.3 11420,-2085 11417.32,-2082.32 11417.32,-2045 11417.32,147.68 11395,170 11394.29,169.29 11325,169.29 -139.88,169.29 -140,169.18
GND on GND "GND" (hatched 90Degree grid 5 track 5, remove dead copper, pour order 1002): -110,169.18 -180.82,169.18 -195,155 -196.85,153.15 -196.85,129 -196.85,-2068.15 -160,-2105 -158.7,-2106.3 -95,-2106.3 11388.7,-2106.3 11415,-2080 11417.32,-2077.68 11417.32,-2040 11417.32,147.68 11395,170 11394.29,169.29 11330,169.29 -109.88,169.29 -110,169.18
GND on Top "GND" (hatched 90Degree grid 5 track 5, remove dead copper, pour order 1000): -130,169.18 -153.55,169.18 -180.82,169.18 -195,155 -196.85,153.15 -196.85,129 -196.85,-2068.15 -160,-2105 -158.7,-2106.3 -95,-2106.3 11388.7,-2106.3 11415,-2080 11417.32,-2077.68 11417.32,-2050 11417.32,142.68 11390,170 11389.29,169.29 11335,169.29 -129.88,169.29 -130,169.18

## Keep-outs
Keep-Out Layer:
  pour cut-out: 8690,-1105 8670,-1125 8670,-1255 8660,-1265 8660,-1370 8500,-1530 8500,-1615 8490,-1625 8420,-1625 8420,-1805 8430,-1815 8810,-1815 8835,-1790 8835,-1535 8950,-1420 8950,-1395 8965,-1380 8965,-1270 8990,-1245 8990,-1110 8985,-1105
  pour cut-out: 4305,-1620 4675,-1620 4685,-1630 4685,-1830 4700,-1845 4690,-1855 4350,-1855 4305,-1810
  pour cut-out: 7955,-1080 7955,-1765 8010,-1820 8405,-1820 8420,-1805 8420,-1555 8280,-1415 8280,-1080
  pour cut-out: 3880,-1620 3880,-1910 4050,-2080 9535,-2080 9730,-1885 9730,-1560 9870,-1420 9930,-1420 10045,-1305 10045,-670 10040,-665 9370,-665 9355,-680 9355,-1465 9400,-1510 9400,-1850 9320,-1930 4785,-1930 4700,-1845 4690,-1855 4350,-1855 4305,-1810 4305,-1620
  pour cut-out: 4080,-1085 4085,-1080 4425,-1080 4435,-1090 4435,-1240 4480,-1285 4480,-1560 4080,-1560
  pour cut-out: 2595,-1830 2760,-1995 3635,-1995 3740,-1890 3740,-1590 3770,-1560 5145,-1560 5215,-1630 5215,-1850 5305,-1940 6015,-1940 6110,-1845 6110,-1125 5415,-1125 5415,-1327.45 5387.45,-1355 3650,-1355 3520,-1485 3520,-1770 3485,-1805 3025,-1805 3015,-1795 3015,-1635 2975,-1595 2595,-1595
  pour cut-out: 1946,-704 1946,-1274 1990,-1318 1990,-1622 2196,-1828 2636,-1828 2636,-703 2635,-704
  pour cut-out: 4674,-1825 4702,-1853 4702,-1867 4699,-1870 4674,-1870
  lines w5: 188.07,169.18 -153.55,169.18 ccw(c-155.11,127.44) -196.85,129 -196.85,-1995 -196.85,-2045 ccw(c-132.78,-2042.22) -130,-2106.3 11365,-2106.3 ccw(c11368.01,-2056.99) 11417.32,-2060 11417.32,-2025 11417.32,118 ccw(c11362.02,113.98) 11358,169.29 10090.55,169.29 10090.55,110.24 7944.09,110.24 7944.09,169.29 6212.6,169.29 6212.6,110.24 4066.14,110.24 4066.14,169.29 2334.25,169.29 2334.25,110.24 188.19,110.24 188.19,169.29

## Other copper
Top:
  pour cut-out: 1686.56,-984 1845.44,-984 1845.44,-968.44 1837,-960 1695,-960 1686.56,-968.44
  region net 12VIN: 7155,-225 7295,-225 7295,-335 7155,-335
  pour cut-out: -10,-1605 1565,-1605 1565,-1800 -10,-1800
  region net B3V3D: 702.5,-1227.5 702.5,-1297.5 682.5,-1317.5 602.5,-1317.5 602.5,-1482.5 667.5,-1547.5 802.5,-1547.5 872.5,-1477.5 872.5,-1317.5 867.5,-1312.5 787.5,-1312.5 767.5,-1292.5 767.5,-1227.5
  region net 12VIN: 315,-730 315,-745 305,-755 40,-755 40,-880 450,-880 450,-735 440,-725 420,-725 415,-730 415,-790 410,-795 400,-795 395,-790 395,-735 390,-730 370,-730 365,-735 365,-790 360,-795 350,-795 345,-790 345,-730
  region net 12VIN: 3185,-385 3525,-385 3560,-350 3685,-350 3685,-380 3620,-380 3615,-385 3615,-395 3620,-400 3685,-400 3685,-430 3620,-430 3615,-435 3615,-445 3620,-450 3685,-450 3685,-475 3680,-480 3355,-480 3340,-495 3180,-495 3185,-440
  region net NetC11_2: 6945,-270 6880,-270 6880,-195 6945,-130 6945,45 6950,50 7010,50 7015,45 7015,-140 6945,-210
  region net 12VIN: 6883.66,-283.18 6883.66,-313.18 6953.66,-313.18 6958.66,-318.18 7048.66,-318.18 7063.66,-333.18 7168.66,-333.18 7168.66,-223.18 7025,-235 6953.66,-283.18
  region net A3V3D: 3852.5,-800 3927.5,-800 3937.5,-810 3937.5,-905 4092.5,-905 4172.5,-825 4172.5,-710 4107.5,-645 3932.5,-645 3932.5,-750 3852.5,-750 3852.5,-800
  region net C3V3D: 8122.5,-740 8197.5,-740 8212.5,-725 8212.5,-635 8362.5,-635 8437.5,-710 8437.5,-825 8367.5,-895 8212.5,-895 8212.5,-805 8197.5,-790 8122.5,-790 8122.5,-740
  region net 12VIN: 10255,-675 10255,-715 10090,-880 10090,-1230 10140,-1280 10450,-1280 10450,-1100 10185,-1100 10180,-1095 10180,-915 10345,-750 10345,-675
  region net 12VIN: 10370,-650 10410,-690 10600,-690 10625,-715 10625,-885 10550,-885 10465,-800 10255,-800 10255,-650
  region net 12VIN: 10240,-240 10240,-635 10280,-675 10395,-675 10395,-240
  region net NetJP3_B1: 8385,-165 8130,-165 8030,-265 8030,-435 8150,-435 8150,-325 8210,-265 8395,-265 8395,-175
  region net 12VIN: 7490,-290 7490,-390 7875,-390 7880,-385 7875,-380 7875,-260 7765,-260 7735,-290
  region net F3V3D: 6137.5,-280 6212.5,-205 6367.5,-205 6367.5,-285 6392.5,-310 6462.5,-310 6462.5,-370 6382.5,-370 6367.5,-385 6367.5,-470 6212.5,-470 6137.5,-395
  region net 12VIN: 7070,-225 7220,-225 7230,-235 7230,-325 7220,-335 7070,-335
  region net 5V0: 6405,-115 6550,-115 6555,-120 6555,-180 6545,-190 6405,-190
  pour cut-out: 6810,45 6945,45 6945,-130 6810,-130
  pour cut-out: 10795,-680 10610,-680 10605,-685 10605,-900 10785,-900 10795,-890
  pour cut-out: 10410,-1070 10505,-1070 10505,-1110 10510,-1115 10510,-1300 10505,-1305 10410,-1305
  pour cut-out: 6375,-235 6485,-235 6490,-240 6490,-340 6485,-345 6480,-340 6375,-340
  region net CON12VB: 10630,-1090 10575,-1145 10480,-1145 10485,-1150 10485,-1295 10590,-1295 10605,-1310 10605,-1485 10580,-1510 10380,-1510 10380,-1725 11030,-1725 11030,-1530 11010,-1510 10815,-1510 10775,-1470 10775,-1200 10730,-1155 10730,-1115 10705,-1090
  region net CON12VA: 10935,-700 10885,-750 10770,-750 10765,-755 10765,-885 10775,-895 10905,-895 10905,-1290 11090,-1475 11090,-1755 11055,-1790 10420,-1790 10365,-1845 10365,-2020 10415,-2070 11140,-2070 11235,-1975 11235,-1460 11025,-1250 11025,-720 11005,-700
  region net 12VIN: 10395,-240 10545,-240 10545,-385 10535,-395 10395,-395
Bottom:
  region net NetJP2_B1: 845.24,-165.21 440.24,-165.21 310.24,-295.21 310.24,-505.21 495.24,-505.21 495.24,-440.21 460.24,-405.21 460.24,-290.21 485.24,-265.21 845.24,-265.21
  region net NetJP1_B1: 4723.15,-175.84 4248.15,-175.84 4133.15,-290.84 4090,-335 4080,-345 3925,-345 3925,-545 4060,-545 4090,-515 4133.15,-470.84 4338.15,-265.84 4723.15,-265.84

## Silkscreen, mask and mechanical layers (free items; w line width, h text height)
Silkscreen Top:
  drawing of 469 lines, arcs and shapes, not listed
  text "GN-1846-A-V2" at 2990,-1095 h27.56
  text "2018-01-02" at 2991,-1167.85 h27.56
